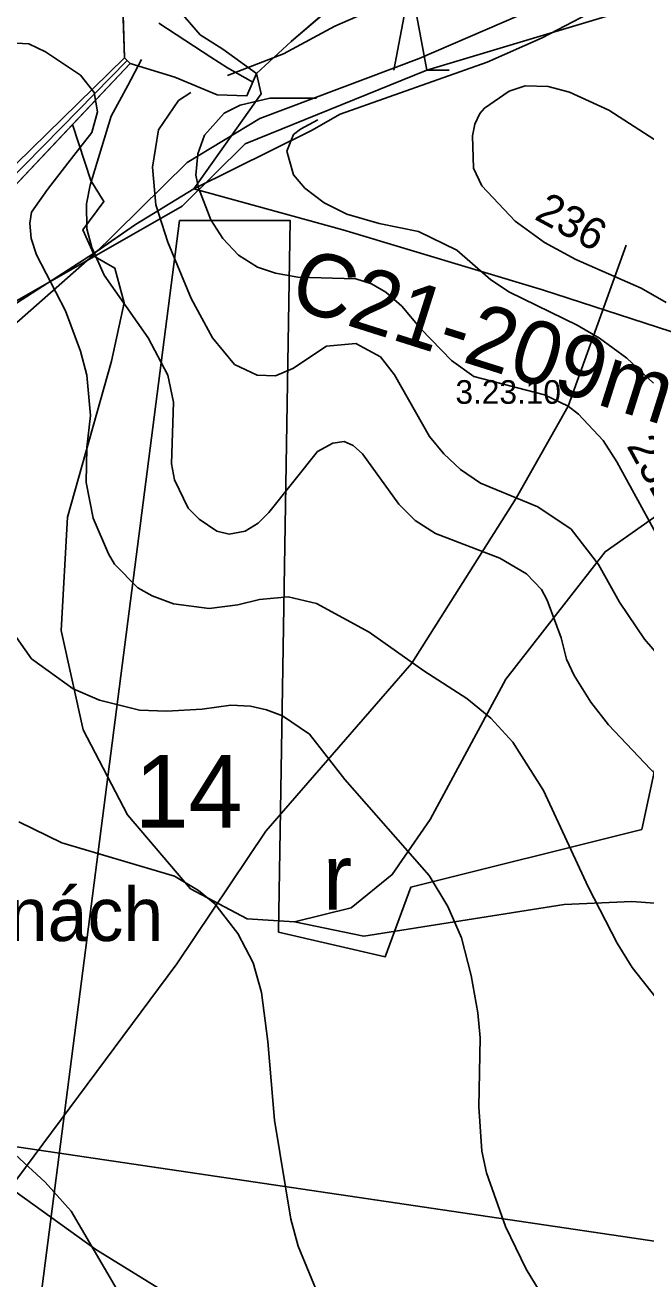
# Model space of a CAD drawing. Extents: x -662500 to -653478, y -1056827 to -1049993.
# Drawn here: x -660352.4 to -660155.6, y -1053566.3 to -1053168.4 of the extents above; entities that cross this region are included whole.
import ezdxf

# ---------------------------------------------------------------- set-up
doc = ezdxf.new("R2010")
doc.units = 0
for name, color, linetype in [('58', 7, 'Continuous'), ('Vrstva 12', 7, 'Continuous'), ('Vrstva 15', 7, 'Continuous'), ('Vrstva 16', 7, 'Continuous'), ('Vrstva 24', 7, 'Continuous'), ('Vrstva 30', 7, 'Continuous'), ('Vrstva 32', 7, 'Continuous'), ('Vrstva 37', 7, 'Continuous'), ('Vrstva 5', 7, 'Continuous'), ('Vrstva 50', 7, 'Continuous'), ('Vrstva 57', 7, 'Continuous'), ('Vrstva 7', 7, 'Continuous')]:
    doc.layers.add(name, color=color, linetype=linetype)

msp = doc.modelspace()

# ---------------------------------------------------------------- linework, layer by layer
at = {"layer": 'Vrstva 12'}
msp.add_lwpolyline([(-660309.98, -1053167.72), (-660293.51, -1053178.59), (-660288.23, -1053181.91), (-660280.22, -1053186.45)], dxfattribs=at)
at = {"layer": 'Vrstva 15'}
for points in [[(-660598.86, -1053031.22), (-660605.75, -1053143.15), (-660610.52, -1053156.43), (-660584.23, -1053223.36), (-660520.18, -1053363.22), (-660506.25, -1053380.34), (-660360.14, -1053523.67), (-660130.71, -1053557.64)], [(-660298.9, -1053220.33), (-660251.66, -1053233.38), (-660188.33, -1053252.39), (-660099.11, -1053281.42)]]:
    msp.add_lwpolyline(points, dxfattribs=at)
at = {"layer": 'Vrstva 24'}
for points in [[(-660331, -1053241.5), (-660301, -1053212), (-660278, -1053198), (-660227.5, -1053179), (-660190.5, -1053163), (-660174, -1053153.5), (-660166, -1053148.5), (-660158, -1053138.5), (-660146, -1053116.5), (-660094.29, -1053000), (-660092.5, -1052996), (-660076, -1052973.5), (-660055.5, -1052958.5), (-660034, -1052954)], [(-660386.5, -1053281), (-660376, -1053278.5), (-660360.5, -1053267.5), (-660331, -1053241.5)], [(-660331, -1053241.5), (-660324, -1053245.5), (-660321, -1053256.5), (-660325, -1053275), (-660339, -1053324.5), (-660341, -1053360.5), (-660334, -1053392), (-660320, -1053419), (-660300, -1053442.5), (-660282, -1053452), (-660267, -1053453)], [(-660267, -1053453), (-660249, -1053448.5), (-660236, -1053438), (-660224, -1053420.5), (-660200, -1053376), (-660168.5, -1053335.5), (-660148.5, -1053321.5), (-660109.5, -1053312), (-660081, -1053315.5)], [(-660267, -1053453), (-660245, -1053457.5), (-660181.5, -1053447.5), (-660160, -1053446.5), (-660126.5, -1053449), (-660086, -1053456), (-660070, -1053459.5), (-660043.5, -1053470), (-660010, -1053485.5), (-660000, -1053490.5), (-659990, -1053495.5), (-659964, -1053526), (-659956.84, -1053531.01), (-659954, -1053533), (-659924.5, -1053540.5), (-659867, -1053533), (-659839, -1053534), (-659815, -1053542.5), (-659799, -1053551.5), (-659769.5, -1053583.5)], [(-659687, -1053701.5), (-659711, -1053686.5), (-659734.5, -1053680.5), (-659814, -1053669.5), (-659908, -1053649.5), (-659980.14, -1053645.8), (-660000, -1053644.78), (-660005.5, -1053644.5), (-660060, -1053634), (-660183.5, -1053621), (-660246.5, -1053605.5), (-660263.5, -1053598), (-660330, -1053557), (-660364, -1053532.5), (-660389, -1053520), (-660401.5, -1053515), (-660430, -1053509.5)]]:
    msp.add_lwpolyline(points, dxfattribs=at)
msp.add_lwpolyline([(-660159.28, -1053125.93), (-660162.29, -1053124.36), (-660173.45, -1053120.87), (-660195.12, -1053121.66), (-660216.31, -1053120.87), (-660245.66, -1053113.43), (-660281.35, -1053120.12), (-660302.14, -1053126.44), (-660312.07, -1053128.99), (-660317.72, -1053134.2), (-660322.02, -1053144.73), (-660320.88, -1053178.8), (-660319.15, -1053180.6), (-660304.97, -1053184.86), (-660291.54, -1053190.52), (-660282.09, -1053190.79), (-660279.01, -1053183.69), (-660268.02, -1053173.58), (-660247.63, -1053156.17), (-660244.16, -1053154.52), (-660239.78, -1053153.33), (-660215.8, -1053151.27), (-660186.01, -1053147.33), (-660158.67, -1053133.25)], close=True, dxfattribs=at)
at = {"layer": 'Vrstva 30'}
msp.add_lwpolyline([(-660322.02, -1053144.73), (-660317.71, -1053134.2), (-660312.07, -1053128.99), (-660302.14, -1053126.44), (-660281.35, -1053120.12), (-660245.66, -1053113.43), (-660216.31, -1053120.87), (-660195.12, -1053121.66), (-660173.45, -1053120.87), (-660162.29, -1053124.36), (-660159.28, -1053125.93), (-660158.67, -1053133.25), (-660186.01, -1053147.33), (-660215.8, -1053151.27), (-660239.78, -1053153.33), (-660244.16, -1053154.52), (-660247.64, -1053156.17), (-660268.02, -1053173.58), (-660279.01, -1053183.69), (-660289.71, -1053175.98), (-660296.94, -1053171.46), (-660303.07, -1053164.35)], close=True, dxfattribs=at)
at = {"layer": 'Vrstva 32'}
msp.add_lwpolyline([(-660732.59, -1053594.34), (-660658.93, -1053520.19), (-660602.39, -1053463.45), (-660566.95, -1053428.59), (-660489, -1053349.86), (-660473.49, -1053335.13), (-660419.3, -1053279.86), (-660364.42, -1053224.74), (-660340.86, -1053200.88), (-660320.07, -1053179.63)], dxfattribs=at)
at = {"layer": 'Vrstva 37'}
msp.add_lwpolyline([(-660303.5, -1053230.44), (-660268.36, -1053230.44), (-660272.06, -1053456.27), (-660238.23, -1053464.08), (-660230.1, -1053441.95), (-660156.9, -1053423.64), (-660133.56, -1053315.41), (-660112.26, -1053315.31), (-660122.32, -1053372.39), (-660125.43, -1053404.18), (-660127.57, -1053442.13), (-660131.64, -1053497.5), (-660136.95, -1053566.03), (-660150.34, -1053712.33), (-660162.69, -1053835.19), (-660383.93, -1053811.56), (-660351.89, -1053606.5)], close=True, dxfattribs=at)
at = {"layer": 'Vrstva 5'}
for points in [[(-660431.05, -1053119.87), (-660413.65, -1053119.9), (-660386.36, -1053118.03), (-660367.74, -1053113.11), (-660337.3, -1053100.08), (-660334.61, -1053117.6), (-660333.75, -1053129.01), (-660329.61, -1053143.08), (-660326.99, -1053149.05), (-660321.61, -1053156.83), (-660320.88, -1053178.8), (-660379.98, -1053236.49), (-660420.58, -1053278.12), (-660486.45, -1053344.24), (-660439.88, -1053269.34), (-660422.63, -1053240.33), (-660403.25, -1053217.61), (-660396.56, -1053206.91), (-660397.57, -1053191.93), (-660412.06, -1053168.45), (-660425.04, -1053150.39), (-660428.77, -1053140.23)], [(-660320.88, -1053178.8), (-660322.02, -1053144.73), (-660317.71, -1053134.2), (-660312.07, -1053128.99), (-660302.14, -1053126.44), (-660281.35, -1053120.12), (-660245.66, -1053113.43), (-660216.31, -1053120.87), (-660195.12, -1053121.66), (-660173.45, -1053120.87), (-660162.29, -1053124.36), (-660159.28, -1053125.93), (-660158.67, -1053133.25), (-660186.01, -1053147.33), (-660215.8, -1053151.27), (-660239.78, -1053153.33), (-660244.16, -1053154.52), (-660247.68, -1053155.93), (-660268.02, -1053173.58), (-660279.01, -1053183.69), (-660282.09, -1053190.79), (-660291.54, -1053190.52), (-660304.97, -1053184.86), (-660319.15, -1053180.6)], [(-660261.56, -1053201.85), (-660298.9, -1053220.33), (-660277.59, -1053190.2), (-660279.01, -1053183.69), (-660268.02, -1053173.58), (-660247.68, -1053155.93), (-660244.16, -1053154.52), (-660239.78, -1053153.33), (-660215.8, -1053151.27), (-660186.01, -1053147.33), (-660158.67, -1053133.25), (-660133.92, -1053118.5), (-660134.88, -1053146.27), (-660138.22, -1053150.5), (-660169, -1053162.26), (-660188.45, -1053172.43), (-660205.94, -1053180.18), (-660252.52, -1053196.63)], [(-660330.71, -1053240.91), (-660334.1, -1053233.32), (-660327.45, -1053224.37), (-660331.54, -1053217.73), (-660337.37, -1053199.91), (-660319.15, -1053180.6), (-660304.97, -1053184.86), (-660291.54, -1053190.52), (-660282.09, -1053190.79), (-660279.01, -1053183.69), (-660277.59, -1053190.2), (-660298.9, -1053220.33), (-660317.42, -1053231.7)], [(-660408.83, -1053280.91), (-660381.05, -1053271.05), (-660356.59, -1053257.53), (-660330.71, -1053240.91), (-660334.1, -1053233.32), (-660327.45, -1053224.37), (-660331.54, -1053217.73), (-660337.37, -1053199.91), (-660375.12, -1053239.93), (-660417.48, -1053281.3), (-660461.06, -1053325.77), (-660424.76, -1053291.44)]]:
    msp.add_lwpolyline(points, close=True, dxfattribs=at)
for points in [[(-660235.48, -1053182.72), (-660230.23, -1053154.72), (-660224.98, -1053182.72), (-660217.98, -1053182.72)], [(-660169, -1053162.26), (-660188.45, -1053172.43), (-660205.94, -1053180.18), (-660252.52, -1053196.63), (-660261.56, -1053201.85), (-660298.9, -1053220.33), (-660317.42, -1053231.7), (-660329.86, -1053240.36), (-660330.71, -1053240.91), (-660356.59, -1053257.53)], [(-660650.77, -1053508.27), (-660618.91, -1053475.06), (-660553.77, -1053409.82), (-660549.91, -1053405.95), (-660540.78, -1053396.88), (-660517.5, -1053373.37), (-660512.28, -1053368.1), (-660486.45, -1053344.24), (-660420.58, -1053278.12), (-660379.98, -1053236.49), (-660320.88, -1053178.8), (-660319.15, -1053180.6), (-660375.12, -1053239.93), (-660417.48, -1053281.3), (-660482.7, -1053347.71), (-660506.84, -1053374.34), (-660512.15, -1053378.66), (-660534.98, -1053401.96), (-660550.52, -1053417.41), (-660613.36, -1053480.06), (-660621.85, -1053488.15), (-660667.78, -1053533.76)]]:
    msp.add_lwpolyline(points, dxfattribs=at)
at = {"layer": 'Vrstva 50'}
msp.add_lwpolyline([(-660435.07, -1052998.4), (-660338.47, -1052921.22), (-660327.47, -1053057.73), (-660321.24, -1053097.21), (-660175.03, -1053103.15), (-660174.83, -1053022.87), (-660135.14, -1053024.72), (-660124.45, -1053106.32), (-660064.14, -1053121.91), (-660064.92, -1053137.67), (-660124.48, -1053141.31), (-660143.9, -1053158.22), (-660224.98, -1053182.72), (-660282.65, -1053206.04), (-660302.63, -1053225.87), (-660408.17, -1053286.14), (-660457.22, -1053301.47), (-660422.63, -1053240.33), (-660404.5, -1053207.93), (-660439.36, -1053118.83)], close=True, dxfattribs=at)
at = {"layer": 'Vrstva 57'}
msp.add_lwpolyline([(-660161.77, -1053238.23), (-660180.21, -1053289.29), (-660196.67, -1053318.48), (-660229.8, -1053370.88), (-660276.09, -1053424.22), (-660304.29, -1053466.28), (-660392.17, -1053584.48), (-660428.83, -1053640.88), (-660463.61, -1053696.33), (-660547.26, -1053782.81)], dxfattribs=at)
at = {"layer": 'Vrstva 7'}
for p, q in [((-660254.18, -1053168.77), (-660241.13, -1053162.97)), ((-660270.48, -1053177.47), (-660254.18, -1053168.77)), ((-660351.26, -1053174.36), (-660366.57, -1053173.51)), ((-660345.99, -1053176.82), (-660351.26, -1053174.36)), ((-660334.87, -1053184.32), (-660345.99, -1053176.82)), ((-660288.24, -1053184.35), (-660270.48, -1053177.47)), ((-660315.52, -1053179.29), (-660319.82, -1053187.55)), ((-660330.52, -1053189.76), (-660334.87, -1053184.32)), ((-660329.44, -1053195.92), (-660330.52, -1053189.76)), ((-660319.82, -1053187.55), (-660325.18, -1053197.32)), ((-660299.83, -1053189.79), (-660303.82, -1053192.33)), ((-660198.91, -1053189.38), (-660206.71, -1053194.77)), ((-660193.81, -1053187.68), (-660198.91, -1053189.38)), ((-660186.58, -1053187.82), (-660193.81, -1053187.68)), ((-660179.78, -1053189.66), (-660186.58, -1053187.82)), ((-660167.31, -1053195.33), (-660179.78, -1053189.66)), ((-660303.82, -1053192.33), (-660310.16, -1053201.57)), ((-660289.33, -1053196.32), (-660284.25, -1053193.78)), ((-660284.25, -1053193.78), (-660274.83, -1053191.6)), ((-660274.83, -1053191.6), (-660259.98, -1053191.6)), ((-660325.18, -1053197.32), (-660331.84, -1053219.14)), ((-660331.25, -1053202.44), (-660329.44, -1053195.92)), ((-660295.57, -1053203.27), (-660289.33, -1053196.32)), ((-660208.27, -1053196.47), (-660209.83, -1053199.87)), ((-660206.71, -1053194.77), (-660208.27, -1053196.47)), ((-660135.57, -1053215.88), (-660167.31, -1053195.33)), ((-660310.16, -1053201.57), (-660312, -1053213.47)), ((-660267.34, -1053203.15), (-660265.05, -1053201.39)), ((-660265.05, -1053201.39), (-660259.61, -1053198.49)), ((-660209.83, -1053199.87), (-660210.54, -1053203.55)), ((-660338.86, -1053212.22), (-660331.25, -1053202.44)), ((-660297.69, -1053209.22), (-660295.57, -1053203.27)), ((-660269.45, -1053208.37), (-660267.34, -1053203.15)), ((-660210.54, -1053203.55), (-660210.25, -1053213.76)), ((-660298.26, -1053216.02), (-660297.69, -1053209.22)), ((-660267.36, -1053215.88), (-660269.45, -1053208.37)), ((-660345.38, -1053220.55), (-660338.86, -1053212.22)), ((-660312, -1053213.47), (-660311.01, -1053225.38)), ((-660210.25, -1053213.76), (-660207.56, -1053219.42)), ((-660297.41, -1053219.99), (-660298.26, -1053216.02)), ((-660263.68, -1053220.13), (-660267.36, -1053215.88)), ((-660350.45, -1053227.8), (-660345.38, -1053220.55)), ((-660331.84, -1053219.14), (-660332.98, -1053225.09)), ((-660293.58, -1053230.19), (-660297.41, -1053219.99)), ((-660257.58, -1053224.81), (-660263.68, -1053220.13)), ((-660207.56, -1053219.42), (-660197.07, -1053230.62)), ((-660332.98, -1053225.09), (-660332.84, -1053233.03)), ((-660311.01, -1053225.38), (-660307.19, -1053237.28)), ((-660250.36, -1053228.35), (-660257.58, -1053224.81)), ((-660350.89, -1053231.29), (-660350.45, -1053227.8)), ((-660240.15, -1053231.33), (-660250.36, -1053228.35)), ((-660350.55, -1053236.15), (-660350.89, -1053231.29)), ((-660332.84, -1053233.03), (-660331.28, -1053238.98)), ((-660289.75, -1053236.15), (-660293.58, -1053230.19)), ((-660227.68, -1053233.88), (-660240.15, -1053231.33)), ((-660215.49, -1053239.83), (-660227.68, -1053233.88)), ((-660197.07, -1053230.62), (-660187.72, -1053237.42)), ((-660348.85, -1053241.25), (-660350.55, -1053236.15)), ((-660307.19, -1053237.28), (-660299.82, -1053255.14)), ((-660284.79, -1053241.39), (-660289.75, -1053236.15)), ((-660187.72, -1053237.42), (-660177.8, -1053242.81)), ((-660339.64, -1053259.1), (-660348.85, -1053241.25)), ((-660331.28, -1053238.98), (-660327.31, -1053247.77)), ((-660278.7, -1053245.22), (-660284.79, -1053241.39)), ((-660204.72, -1053249.18), (-660215.49, -1053239.83)), ((-660273.03, -1053247.06), (-660278.7, -1053245.22)), ((-660177.8, -1053242.81), (-660157.11, -1053251.88)), ((-660327.31, -1053247.77), (-660313.42, -1053267.61)), ((-660265.95, -1053248.33), (-660273.03, -1053247.06)), ((-660247.52, -1053248.9), (-660265.95, -1053248.33)), ((-660242.56, -1053250.46), (-660247.52, -1053248.9)), ((-660198.77, -1053253.15), (-660204.72, -1053249.18)), ((-660238.03, -1053253.15), (-660242.56, -1053250.46)), ((-660232.93, -1053257.54), (-660238.03, -1053253.15)), ((-660177.37, -1053263.64), (-660198.77, -1053253.15)), ((-660157.11, -1053251.88), (-660149.17, -1053256.41)), ((-660299.82, -1053255.14), (-660293.01, -1053267.61)), ((-660226.97, -1053264.77), (-660232.93, -1053257.54)), ((-660334.82, -1053271.86), (-660339.64, -1053259.1)), ((-660217.2, -1053274.83), (-660226.97, -1053264.77)), ((-660170.29, -1053267.75), (-660177.37, -1053263.64)), ((-660313.42, -1053267.61), (-660307.19, -1053279.51)), ((-660293.01, -1053267.61), (-660286.07, -1053276.11)), ((-660256.88, -1053270.3), (-660247.52, -1053269.45)), ((-660247.52, -1053269.45), (-660239.73, -1053273.7)), ((-660161.64, -1053274.13), (-660170.29, -1053267.75)), ((-660332.84, -1053279.51), (-660334.82, -1053271.86)), ((-660267.51, -1053277.39), (-660256.88, -1053270.3)), ((-660239.73, -1053273.7), (-660235.33, -1053279.37)), ((-660286.07, -1053276.11), (-660278.84, -1053279.51)), ((-660273.03, -1053279.65), (-660267.51, -1053277.39)), ((-660210.11, -1053279.94), (-660217.2, -1053274.83)), ((-660153.14, -1053282.06), (-660161.64, -1053274.13)), ((-660331.7, -1053292.27), (-660332.84, -1053279.51)), ((-660307.19, -1053279.51), (-660305.34, -1053288.01)), ((-660278.84, -1053279.51), (-660273.03, -1053279.65)), ((-660235.33, -1053279.37), (-660224.14, -1053298.93)), ((-660187.72, -1053285.75), (-660210.11, -1053279.94)), ((-660305.34, -1053288.01), (-660306.05, -1053307.57)), ((-660180.21, -1053289.29), (-660187.72, -1053285.75)), ((-660176.95, -1053291.84), (-660180.21, -1053289.29)), ((-660332.84, -1053302.47), (-660331.7, -1053292.27)), ((-660169.15, -1053300.2), (-660176.95, -1053291.84)), ((-660259.71, -1053303.74), (-660254.89, -1053301.05)), ((-660254.89, -1053301.05), (-660251.21, -1053300.49)), ((-660251.21, -1053300.49), (-660248.37, -1053301.76)), ((-660224.14, -1053298.93), (-660219.6, -1053304.45)), ((-660164.76, -1053307), (-660169.15, -1053300.2)), ((-660333.12, -1053313.52), (-660332.84, -1053302.47)), ((-660275.16, -1053323.02), (-660259.71, -1053303.74)), ((-660248.37, -1053301.76), (-660245.4, -1053304.45)), ((-660245.4, -1053304.45), (-660233.92, -1053320.47)), ((-660219.6, -1053304.45), (-660214.36, -1053309.41)), ((-660306.05, -1053307.57), (-660305.06, -1053312.67)), ((-660214.36, -1053309.41), (-660207.98, -1053313.81)), ((-660142.37, -1053348.1), (-660164.76, -1053307)), ((-660330.85, -1053324.86), (-660333.12, -1053313.52)), ((-660305.06, -1053312.67), (-660300.67, -1053321.74)), ((-660207.98, -1053313.81), (-660189.84, -1053321.32)), ((-660233.92, -1053320.47), (-660228.68, -1053325.57)), ((-660189.84, -1053321.32), (-660179.21, -1053328.4)), ((-660326.03, -1053336.2), (-660330.85, -1053324.86)), ((-660300.67, -1053321.74), (-660297.27, -1053325.14)), ((-660297.27, -1053325.14), (-660291.6, -1053328.97)), ((-660278.56, -1053326.42), (-660275.16, -1053323.02)), ((-660291.6, -1053328.97), (-660287.77, -1053329.96)), ((-660287.77, -1053329.96), (-660282.67, -1053328.97)), ((-660282.67, -1053328.97), (-660278.56, -1053326.42)), ((-660228.68, -1053325.57), (-660222.3, -1053329.68)), ((-660179.21, -1053328.4), (-660170.57, -1053339.6)), ((-660222.3, -1053329.68), (-660201.89, -1053337.61)), ((-660324.05, -1053339.46), (-660326.03, -1053336.2)), ((-660316.68, -1053346.97), (-660324.05, -1053339.46)), ((-660201.89, -1053337.61), (-660193.39, -1053342.57)), ((-660170.57, -1053339.6), (-660163.91, -1053351.5)), ((-660193.39, -1053342.57), (-660188.71, -1053347.53)), ((-660312.15, -1053349.52), (-660316.68, -1053346.97)), ((-660188.71, -1053347.53), (-660186.87, -1053350.94)), ((-660305.34, -1053352.07), (-660312.15, -1053349.52)), ((-660294.01, -1053353.49), (-660305.34, -1053352.07)), ((-660284.94, -1053352.35), (-660294.01, -1053353.49)), ((-660278.13, -1053350.65), (-660284.94, -1053352.35)), ((-660269.06, -1053349.8), (-660278.13, -1053350.65)), ((-660259.99, -1053351.93), (-660269.06, -1053349.8)), ((-660243.27, -1053361), (-660259.99, -1053351.93)), ((-660186.87, -1053350.94), (-660182.47, -1053362.84)), ((-660163.91, -1053351.5), (-660155.97, -1053363.27)), ((-660357.21, -1053359.86), (-660350.41, -1053369.5)), ((-660225.98, -1053373.33), (-660243.27, -1053361)), ((-660182.47, -1053362.84), (-660180.77, -1053369.64)), ((-660155.97, -1053363.27), (-660151.3, -1053368.65)), ((-660350.41, -1053369.5), (-660337.23, -1053379)), ((-660180.77, -1053369.64), (-660178.36, -1053374.75)), ((-660212.38, -1053382.11), (-660225.98, -1053373.33)), ((-660178.36, -1053374.75), (-660172.98, -1053383.25)), ((-660337.23, -1053379), (-660328.87, -1053382.68)), ((-660328.87, -1053382.68), (-660316.11, -1053385.8)), ((-660296.27, -1053385.52), (-660287.2, -1053384.24)), ((-660287.2, -1053384.24), (-660280.97, -1053384.52)), ((-660280.97, -1053384.52), (-660275.87, -1053385.66)), ((-660204.72, -1053388.35), (-660212.38, -1053382.11)), ((-660172.98, -1053383.25), (-660167.45, -1053390.48)), ((-660316.11, -1053385.8), (-660307.61, -1053386.08)), ((-660307.61, -1053386.08), (-660296.27, -1053385.52)), ((-660275.87, -1053385.66), (-660270.77, -1053387.64)), ((-660270.77, -1053387.64), (-660262.26, -1053393.45)), ((-660197.78, -1053396), (-660204.72, -1053388.35)), ((-660167.45, -1053390.48), (-660145.77, -1053413.43)), ((-660262.26, -1053393.45), (-660251.07, -1053407.76)), ((-660188, -1053411.31), (-660197.78, -1053396)), ((-660251.07, -1053407.76), (-660224.28, -1053438.23)), ((-660173.83, -1053441.92), (-660188, -1053411.31)), ((-660354.38, -1053421.23), (-660340.77, -1053427.89)), ((-660340.77, -1053427.89), (-660305.06, -1053438.52)), ((-660305.06, -1053438.52), (-660297.41, -1053443.05)), ((-660224.28, -1053438.23), (-660218.33, -1053448.15)), ((-660297.41, -1053443.05), (-660292.31, -1053447.3)), ((-660164.62, -1053459.77), (-660173.83, -1053441.92)), ((-660292.31, -1053447.3), (-660284.94, -1053456.66)), ((-660218.33, -1053448.15), (-660214.08, -1053458.07)), ((-660284.94, -1053456.66), (-660280.12, -1053466.01)), ((-660214.08, -1053458.07), (-660210.96, -1053469.98)), ((-660159.94, -1053467.43), (-660164.62, -1053459.77)), ((-660280.12, -1053466.01), (-660277.43, -1053475.36)), ((-660150.87, -1053479.05), (-660159.94, -1053467.43)), ((-660210.96, -1053469.98), (-660208.83, -1053481.88)), ((-660277.43, -1053475.36), (-660275.44, -1053490.95)), ((-660208.83, -1053481.88), (-660208.13, -1053489.82)), ((-660275.44, -1053490.95), (-660273.32, -1053515.89)), ((-660208.13, -1053489.82), (-660208.55, -1053511.64)), ((-660208.55, -1053511.64), (-660207.56, -1053525.81)), ((-660273.32, -1053515.89), (-660268.21, -1053547.35)), ((-660355.51, -1053526.95), (-660346.02, -1053535.59)), ((-660207.56, -1053525.81), (-660206.14, -1053532.62)), ((-660346.02, -1053535.59), (-660337.8, -1053544.8)), ((-660206.14, -1053532.62), (-660200.05, -1053549.62)), ((-660337.8, -1053544.8), (-660311.72, -1053589.45)), ((-660268.21, -1053547.35), (-660265.8, -1053555.86)), ((-660200.05, -1053549.62), (-660193.53, -1053563.23)), ((-660265.8, -1053555.86), (-660258.86, -1053572.86)), ((-660193.53, -1053563.23), (-660177.23, -1053589.87))]:
    msp.add_line(p, q, dxfattribs=at)

# ---------------------------------------------------------------- texts
at = {"layer": '58'}
msp.add_text('Na novinách', height=17, dxfattribs=at).set_placement((-660435.01, -1053459.07))
at = {"layer": 'Vrstva 16'}
msp.add_text('C21-209m', height=20, rotation=342.42, dxfattribs=at).set_placement((-660269.45, -1053257.59))
at = {"layer": 'Vrstva 24'}
msp.add_text('3.23.10', height=7.5, dxfattribs=at).set_placement((-660215.96, -1053288.57))
at = {"layer": 'Vrstva 5'}
msp.add_text('r', height=21, dxfattribs=at).set_placement((-660258.02, -1053449.16))
at = {"layer": 'Vrstva 57'}
msp.add_text('14', height=23, dxfattribs=at).set_placement((-660317.69, -1053423.05))
at = {"layer": 'Vrstva 7'}
for s, rotation, p in [('236', 331.505, (-660191.29, -1053229.79)), ('232', 298.5841, (-660161.84, -1053301.91))]:
    msp.add_text(s, height=10, rotation=rotation, dxfattribs=at).set_placement(p)

doc.saveas('drawing.dxf')
